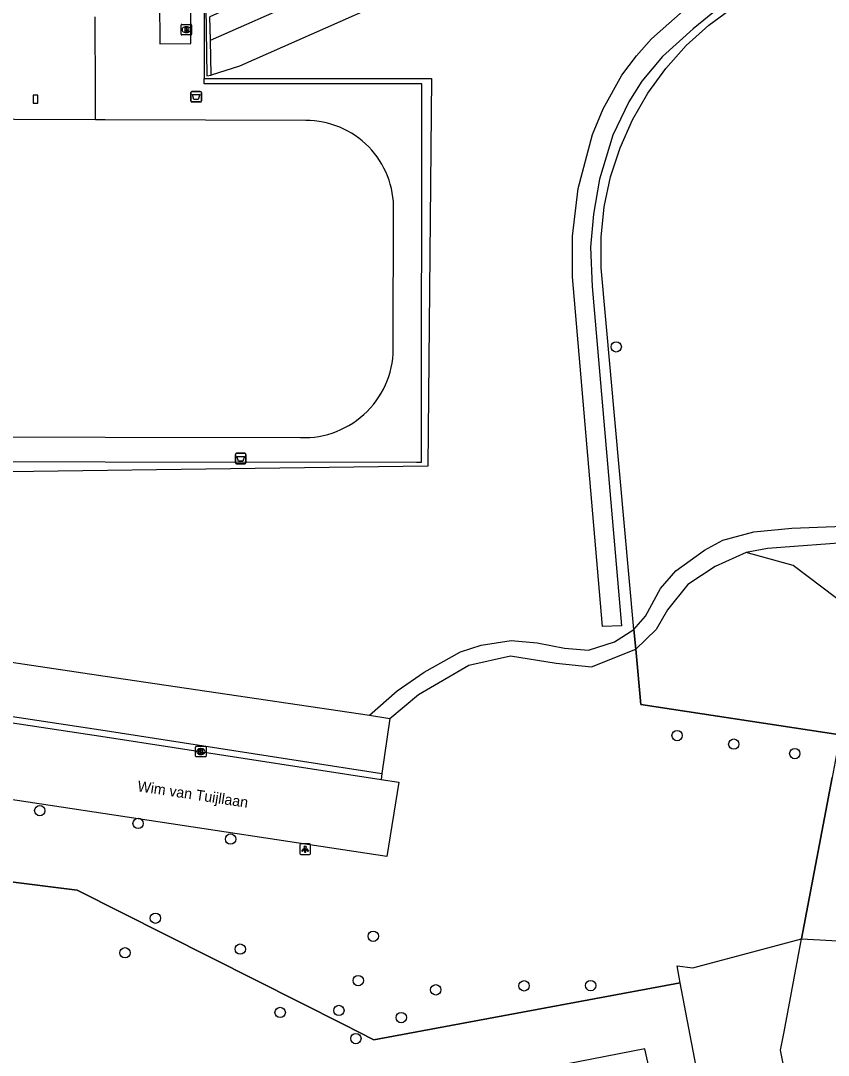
# Model space of a CAD drawing. Extents: x 160203 to 161526, y 379529 to 381797.
# Drawn here: x 160992 to 161068.4, y 380497.8 to 380595.6 of the extents above; entities that cross this region are included whole.
import ezdxf

# ---------------------------------------------------------------- set-up
doc = ezdxf.new("R2010")
doc.units = 0
for name, color, linetype in [('IMGEO_Afvalbak', 7, 'Continuous'), ('IMGEO_Boom', 7, 'Continuous'), ('IMGEO_Brandkraan', 7, 'Continuous'), ('IMGEO_Groenvoorziening', 7, 'Continuous'), ('IMGEO_Haag', 7, 'Continuous'), ('IMGEO_Hek', 7, 'Continuous'), ('IMGEO_Kademuur', 7, 'Continuous'), ('IMGEO_Kolk', 7, 'Continuous'), ('IMGEO_Lichtpunt', 7, 'Continuous'), ('IMGEO_Loofbos', 7, 'Continuous'), ('IMGEO_Open_loods', 7, 'Continuous'), ('IMGEO_Openbare_ruimte_label', 7, 'Continuous'), ('IMGEO_Parkeervlak_gesloten', 7, 'Continuous'), ('IMGEO_Rijbaan_lokaal_open', 7, 'Continuous'), ('IMGEO_Voetpad_gesloten', 7, 'Continuous'), ('IMGEO_Voetpad_halfverhard', 7, 'Continuous'), ('IMGEO_Voetpad_open', 7, 'Continuous'), ('IMGEO_Waterloop', 7, 'Continuous')]:
    doc.layers.add(name, color=color, linetype=linetype)

msp = doc.modelspace()

# ---------------------------------------------------------------- linework, layer by layer
at = {"layer": 'IMGEO_Afvalbak'}
for p, q in [((161008.103, 380588.053), (161008.103, 380588.853)), ((161008.103, 380588.853), (161008.103, 380588.053)), ((161008.203, 380588.953), (161008.993, 380588.953)), ((161008.993, 380588.953), (161008.203, 380588.953)), ((161009.093, 380588.853), (161009.093, 380588.053)), ((161009.093, 380588.053), (161009.093, 380588.853)), ((161008.993, 380587.953), (161008.203, 380587.953)), ((161008.203, 380587.953), (161008.993, 380587.953)), ((161012.315, 380553.824), (161012.315, 380554.624)), ((161012.315, 380554.624), (161012.315, 380553.824)), ((161012.415, 380554.724), (161013.205, 380554.724)), ((161013.205, 380554.724), (161012.415, 380554.724)), ((161013.305, 380554.624), (161013.305, 380553.824)), ((161013.305, 380553.824), (161013.305, 380554.624)), ((161013.205, 380553.724), (161012.415, 380553.724)), ((161012.415, 380553.724), (161013.205, 380553.724))]:
    msp.add_line(p, q, dxfattribs=at)
for points in [[(161008.246, 380588.667), (161008.95, 380588.667), (161008.801, 380588.197), (161008.395, 380588.197), (161008.246, 380588.667)], [(161012.458, 380554.438), (161013.162, 380554.438), (161013.013, 380553.968), (161012.607, 380553.968), (161012.458, 380554.438)]]:
    msp.add_lwpolyline(points, dxfattribs=at)
for centre, start, end in [((161008.203, 380588.853), 90, 180), ((161008.203, 380588.853), 90, 180), ((161008.993, 380588.853), 0, 90), ((161008.993, 380588.853), 360, 90), ((161008.203, 380588.053), 180, 270), ((161008.203, 380588.053), 180, 270), ((161008.993, 380588.053), 270, 0), ((161008.993, 380588.053), 270, 0), ((161012.415, 380554.624), 90, 180), ((161012.415, 380554.624), 90, 180), ((161013.205, 380554.624), 0, 90), ((161013.205, 380554.624), 360, 90), ((161012.415, 380553.824), 180, 270), ((161012.415, 380553.824), 180, 270), ((161013.205, 380553.824), 270, 0), ((161013.205, 380553.824), 270, 0)]:
    msp.add_arc(centre, 0.1, start, end, dxfattribs=at)
at = {"layer": 'IMGEO_Boom'}
for centre in [(161048.317, 380564.79), (161054.082, 380528.026), (161059.436, 380527.217), (161065.208, 380526.318), (160993.815, 380520.926), (161003.116, 380519.722), (161011.856, 380518.24), (161004.748, 380510.754), (161025.347, 380509.044), (161012.772, 380507.832), (161001.873, 380507.483), (161023.931, 380504.855), (161031.256, 380503.98), (161039.606, 380504.358), (161045.905, 380504.38), (161016.545, 380501.838), (161022.094, 380502.027), (161027.997, 380501.351), (161023.704, 380499.364)]:
    msp.add_circle(centre, 0.489, dxfattribs=at)
at = {"layer": 'IMGEO_Brandkraan'}
for p, q in [((161007.244, 380595.292), (161008.096, 380595.292)), ((161007.169, 380594.366), (161007.169, 380595.218)), ((161008.096, 380594.292), (161007.244, 380594.292)), ((161007.68, 380594.512), (161007.655, 380594.512)), ((161007.657, 380595.072), (161007.682, 380595.072)), ((161008.17, 380595.218), (161008.17, 380594.366))]:
    msp.add_line(p, q, dxfattribs=at)
for points in [[(161007.244, 380595.292), (161008.096, 380595.292)], [(161007.169, 380594.366), (161007.169, 380595.218)], [(161008.096, 380594.292), (161007.244, 380594.292)], [(161007.517, 380594.992), (161007.517, 380594.592), (161007.73, 380594.592)], [(161007.748, 380594.992), (161007.517, 380594.992)], [(161007.696, 380594.911), (161007.642, 380594.911), (161007.642, 380594.835)], [(161007.642, 380594.835), (161007.695, 380594.835)], [(161007.704, 380594.759), (161007.642, 380594.759), (161007.642, 380594.678)], [(161007.642, 380594.678), (161007.704, 380594.678)], [(161008.17, 380595.218), (161008.17, 380594.366)]]:
    msp.add_lwpolyline(points, dxfattribs=at)
for centre, radius, start, end in [((161007.246, 380595.216), 0.0765, 91.55205, 178.44795), ((161007.246, 380595.216), 0.0765, 91.55205, 178.44795), ((161008.094, 380595.216), 0.0765, 1.55205, 88.44795), ((161008.094, 380595.216), 0.0765, 1.55205, 88.44795), ((161007.246, 380594.368), 0.0765, 181.55205, 268.44795), ((161007.246, 380594.368), 0.0765, 181.55205, 268.44795), ((161007.697, 380594.873), 0.0379, 267.82845, 90.93552), ((161007.705, 380594.718), 0.0404, 269.87594, 90.50774), ((161007.736, 380594.843), 0.251, 268.66757, 293.53466), ((161007.752, 380594.847), 0.145, 59.4692, 91.53667), ((161007.777, 380594.894), 0.0922, 285.51372, 58.15012), ((161007.782, 380594.702), 0.105, 301.31148, 78.98903), ((161008.094, 380594.368), 0.0765, 271.55205, 358.44795), ((161008.094, 380594.368), 0.0765, 271.55205, 358.44795)]:
    msp.add_arc(centre, radius, start, end, dxfattribs=at)
for centre, major_axis, ratio, start_param, end_param in [((161007.656, 380594.792), (-0.387, 0.002), 0.722429, 4.712389, 7.853982), ((161007.681, 380594.792), (-0.39, 0.002), 0.717154, 1.570796, 4.712389)]:
    msp.add_ellipse(centre, major_axis=major_axis, ratio=ratio, start_param=start_param, end_param=end_param, dxfattribs=at)
at = {"layer": 'IMGEO_Groenvoorziening'}
msp.add_lwpolyline([(161092.862, 380626.998), (161089.63, 380625.323), (161075.362, 380619.305), (161056.631, 380610.785), (161012.701, 380591.353), (161010.016, 380590.501)], dxfattribs=at)
at = {"layer": 'IMGEO_Haag'}
msp.add_lwpolyline([(161009.355, 380590.18), (161030.84, 380590.175), (161030.513, 380553.498), (160974.535, 380552.751)], dxfattribs=at)
at = {"layer": 'IMGEO_Hek'}
for points in [[(161050.001, 380538.062), (161046.892, 380572.26), (161046.889, 380575.157), (161047.188, 380578.039), (161047.787, 380580.874), (161048.679, 380583.631), (161049.855, 380586.279), (161051.3, 380588.79), (161053.001, 380591.136), (161054.937, 380593.292), (161057.088, 380595.233), (161059.43, 380596.939), (161061.937, 380598.391), (161063.565, 380599.157), (161071.462, 380603.433), (161098.612, 380617.08)], [(161050.169, 380536.216), (161050.001, 380538.062)], [(161069.501, 380528.085), (161050.647, 380530.954), (161050.169, 380536.216)], [(161065.849, 380508.788), (161068.738, 380524.054)], [(160997.348, 380513.4), (160969.211, 380516.95)], [(161054.376, 380504.632), (161025.407, 380499.252), (161022.555, 380500.69), (160997.348, 380513.4)], [(161071.584, 380459.183), (161063.859, 380498.271), (161064.187, 380500), (161065.849, 380508.788)], [(161054.068, 380506.244), (161055.556, 380506.056)], [(161066.608, 380440.645), (161054.376, 380504.632), (161054.068, 380506.244)]]:
    msp.add_lwpolyline(points, dxfattribs=at)
at = {"layer": 'IMGEO_Kademuur'}
for points in [[(161009.826, 380599.136), (161009.487, 380599.094), (161009.596, 380590.439), (161010.016, 380590.501)], [(161009.943, 380593.804), (161009.895, 380595.997)], [(161010.016, 380590.501), (161009.943, 380593.804)]]:
    msp.add_lwpolyline(points, dxfattribs=at)
at = {"layer": 'IMGEO_Kolk'}
for p, q in [((161008.538, 380526.092), (161008.538, 380526.944)), ((161008.613, 380527.018), (161009.465, 380527.018)), ((161009.026, 380526.798), (161009.051, 380526.798)), ((161009.539, 380526.944), (161009.539, 380526.092)), ((161009.465, 380526.018), (161008.613, 380526.018)), ((161009.049, 380526.238), (161009.024, 380526.238))]:
    msp.add_line(p, q, dxfattribs=at)
for points in [[(161008.538, 380526.092), (161008.538, 380526.944)], [(161008.613, 380527.018), (161009.465, 380527.018)], [(161009.539, 380526.944), (161009.539, 380526.092)], [(161009.465, 380526.018), (161008.613, 380526.018)], [(161008.859, 380526.718), (161008.982, 380526.718), (161008.982, 380526.567), (161009.112, 380526.718), (161009.276, 380526.718), (161009.13, 380526.567), (161009.283, 380526.318), (161009.131, 380526.318), (161009.046, 380526.482), (161008.982, 380526.415), (161008.982, 380526.318), (161008.859, 380526.318), (161008.859, 380526.718)]]:
    msp.add_lwpolyline(points, dxfattribs=at)
for centre, start, end in [((161008.615, 380526.942), 91.55205, 178.44795), ((161008.615, 380526.942), 91.55205, 178.44795), ((161009.463, 380526.942), 1.55205, 88.44795), ((161009.463, 380526.942), 1.55205, 88.44795), ((161008.615, 380526.094), 181.55205, 268.44795), ((161008.615, 380526.094), 181.55205, 268.44795), ((161009.463, 380526.094), 271.55205, 358.44795), ((161009.463, 380526.094), 271.55205, 358.44795)]:
    msp.add_arc(centre, 0.0765, start, end, dxfattribs=at)
for centre, major_axis, ratio, start_param, end_param in [((161009.025, 380526.518), (-0.387, 0.002), 0.722429, 4.712389, 7.853982), ((161009.05, 380526.518), (-0.39, 0.002), 0.717154, 1.570796, 4.712389)]:
    msp.add_ellipse(centre, major_axis=major_axis, ratio=ratio, start_param=start_param, end_param=end_param, dxfattribs=at)
at = {"layer": 'IMGEO_Lichtpunt'}
for p, q in [((161018.413, 380517.688), (161018.413, 380516.881)), ((161018.413, 380517.688), (161018.413, 380516.881)), ((161019.315, 380517.783), (161018.507, 380517.783)), ((161019.315, 380517.783), (161018.507, 380517.783)), ((161019.409, 380516.881), (161019.409, 380517.688)), ((161019.409, 380516.881), (161019.409, 380517.688)), ((161018.507, 380516.787), (161019.315, 380516.787)), ((161018.507, 380516.787), (161019.315, 380516.787))]:
    msp.add_line(p, q, dxfattribs=at)
for points in [[(161018.787, 380517.352), (161018.826, 380517.324), (161018.638, 380517.062), (161018.6, 380517.089), (161018.787, 380517.352)], [(161018.889, 380517.304), (161018.936, 380517.304), (161018.936, 380516.982), (161018.889, 380516.982), (161018.889, 380517.304)], [(161018.999, 380517.324), (161019.037, 380517.351), (161019.224, 380517.089), (161019.185, 380517.061), (161018.999, 380517.324)]]:
    msp.add_lwpolyline(points, dxfattribs=at)
msp.add_circle((161018.912, 380517.486), 0.0994, dxfattribs=at)
for centre, start, end in [((161018.507, 380517.688), 90, 180), ((161018.507, 380517.688), 90, 180), ((161019.315, 380517.688), 0, 90), ((161019.315, 380517.688), 0, 90), ((161018.507, 380516.881), 180, 270), ((161018.507, 380516.881), 180, 270), ((161019.315, 380516.881), 270, 0), ((161019.315, 380516.881), 270, 360)]:
    msp.add_arc(centre, 0.0946, start, end, dxfattribs=at)
at = {"layer": 'IMGEO_Loofbos'}
for points in [[(161151.663, 380559.856), (161149.809, 380560.422), (161148.111, 380560.705), (161147.184, 380560.783), (161139.902, 380564.161), (161132.57, 380561.521), (161125.881, 380556.731), (161120.038, 380549.051), (161118.235, 380546.156), (161117.164, 380542.115), (161112.955, 380538.902), (161107.161, 380533.448), (161103.947, 380533.448), (161095.669, 380533.448), (161090.58, 380531.058), (161087.61, 380529.159), (161083.373, 380529.159), (161074.252, 380530.662), (161072.904, 380535.976), (161070.469, 380540.017), (161065.065, 380544.108), (161060.622, 380545.329)], [(161050.169, 380536.216), (161050.647, 380530.954), (161069.501, 380528.085), (161068.738, 380524.054), (161065.849, 380508.788)], [(160969.211, 380516.95), (160997.348, 380513.4), (161022.555, 380500.69), (161025.407, 380499.252), (161054.376, 380504.632)], [(161054.376, 380504.632), (161054.068, 380506.244), (161055.556, 380506.056), (161065.849, 380508.788)], [(161071.584, 380459.183), (161063.859, 380498.271), (161064.187, 380500), (161065.849, 380508.788)], [(161065.849, 380508.788), (161095.124, 380507.205), (161101.207, 380496.804), (161106.581, 380489.158), (161112.821, 380486.036), (161120.126, 380484.817), (161135.383, 380484.055)], [(161066.608, 380440.645), (161054.376, 380504.632)]]:
    msp.add_lwpolyline(points, dxfattribs=at)
at = {"layer": 'IMGEO_Open_loods'}
for points in [[(160993.64, 380588.613), (160993.205, 380588.614), (160993.203, 380587.836), (160993.638, 380587.835), (160993.64, 380588.613)], [(160999.085, 380586.28), (160976.111, 380586.373)], [(161018.973, 380586.199), (161000, 380586.276), (160999.085, 380586.28)], [(161027.237, 380565.008), (161027.267, 380577.721)], [(160975.708, 380556.3), (161000, 380556.251), (161018.465, 380556.213)]]:
    msp.add_lwpolyline(points, dxfattribs=at)
for centre, radius, start, end in [((161019.012, 380577.941), 8.258, 358.47159, 90.27132), ((161018.785, 380564.666), 8.459, 267.8303, 2.31973)]:
    msp.add_arc(centre, radius, start, end, dxfattribs=at)
at = {"layer": 'IMGEO_Parkeervlak_gesloten'}
for points in [[(160940.686, 380542.511), (161000, 380533.651), (161024.98, 380529.951)], [(161026.899, 380529.633), (161026.173, 380524.441)]]:
    msp.add_lwpolyline(points, dxfattribs=at)
at = {"layer": 'IMGEO_Rijbaan_lokaal_open'}
for points in [[(160828.18, 380554.482), (161000, 380528.513), (161026.173, 380524.441)], [(160828.089, 380553.895), (161000, 380527.913), (161026.094, 380523.879)], [(161026.094, 380523.879), (161027.779, 380523.619), (161026.638, 380516.587), (161000, 380520.618), (160970.441, 380525.091)], [(161026.173, 380524.441), (161026.094, 380523.879)]]:
    msp.add_lwpolyline(points, dxfattribs=at)
at = {"layer": 'IMGEO_Voetpad_gesloten'}
for points in [[(161009.357, 380600.463), (161009.355, 380590.18)], [(161005.154, 380593.467), (161008.113, 380593.501), (161008.084, 380597.558), (161005.145, 380597.544), (161005.154, 380593.467)], [(160999.085, 380586.28), (160999.079, 380588.766), (160999.062, 380595.993)], [(160974.556, 380553.755), (160974.56, 380553.97), (161000, 380553.934), (161029.421, 380553.892), (161029.796, 380553.891), (161029.912, 380553.891), (161029.94, 380589.66), (161029.824, 380589.66), (161009.355, 380589.664), (161009.355, 380590.18)]]:
    msp.add_lwpolyline(points, dxfattribs=at)
at = {"layer": 'IMGEO_Voetpad_halfverhard'}
for points in [[(161050.001, 380538.062), (161051.094, 380539.336), (161052.513, 380541.948), (161053.96, 380543.623), (161056.657, 380545.553), (161058.406, 380546.515), (161061.337, 380547.31), (161064.913, 380547.658), (161084.433, 380548.403), (161088.698, 380549.105), (161093.665, 380550.794), (161098.483, 380554.073), (161102.357, 380558.942), (161107.473, 380566.345), (161110.734, 380572.672), (161111.727, 380576.995), (161111.131, 380581.218), (161109.293, 380585.292), (161106.766, 380588.683), (161105.276, 380592.061), (161103.29, 380598.42), (161101.432, 380606.57), (161099.65, 380615.748), (161099.2, 380619.612)], [(161110.282, 380585.876), (161112.352, 380581.457), (161112.97, 380577.598), (161113.018, 380576.024), (161112.402, 380573.38), (161111.393, 380570.821), (161109.577, 380567.219), (161107.537, 380564.015), (161101.439, 380555.158), (161099.317, 380552.929), (161097.131, 380551.169), (161094.519, 380549.535), (161089.296, 380547.686), (161085.683, 380546.999), (161081.758, 380546.74), (161071.041, 380546.351), (161062.633, 380545.737), (161060.622, 380545.329)], [(161060.622, 380545.329), (161057.681, 380544.023), (161055.102, 380542.32), (161053.166, 380539.932), (161052.087, 380538.058), (161050.169, 380536.216)], [(161024.98, 380529.951), (161027.619, 380532.25), (161030.174, 380534.01), (161033.608, 380535.941), (161035.538, 380536.566), (161038.376, 380537.02), (161040.831, 380536.814), (161043.442, 380536.303), (161045.685, 380536.12), (161048.145, 380536.889), (161050.001, 380538.062)], [(161050.001, 380538.062), (161050.169, 380536.216)], [(161026.899, 380529.633), (161029.618, 380531.911), (161034.399, 380534.694), (161038.31, 380535.563), (161042.657, 380534.867), (161045.973, 380534.533), (161050.169, 380536.216)], [(161024.98, 380529.951), (161026.899, 380529.633)]]:
    msp.add_lwpolyline(points, dxfattribs=at)
at = {"layer": 'IMGEO_Voetpad_open'}
msp.add_lwpolyline([(161066.608, 380440.645), (161066.33, 380440.623), (161063.889, 380442.387), (161063.307, 380444.833), (161051.214, 380497.538), (161051.027, 380498.401), (160975.678, 380483.713)], dxfattribs=at)
at = {"layer": 'IMGEO_Waterloop'}
for points in [[(161009.943, 380593.804), (161062.339, 380616.92), (161090.054, 380628.954), (161091.21, 380629.729), (161091.337, 380630.37), (161091.256, 380630.519), (161091.915, 380630.792), (161091.4, 380631.789), (161090.762, 380631.536), (161090.661, 380631.756), (161089.88, 380631.882), (161065.601, 380621.17), (161009.895, 380595.997)], [(161050.23, 380592.304), (161051.665, 380593.915), (161055.472, 380597.303), (161062.72, 380602.112), (161066.147, 380604.104), (161097.422, 380620.092)], [(161098.311, 380617.986), (161065.436, 380601.414), (161060.994, 380598.8), (161057.973, 380596.783), (161055.612, 380594.88), (161052.693, 380592.253), (161050.738, 380589.918), (161049.507, 380587.964), (161048.009, 380584.83), (161046.752, 380580.656), (161046.181, 380577.357), (161045.902, 380574.21), (161046.054, 380570.492), (161048.834, 380538.421), (161047.032, 380538.335), (161044.176, 380571.431), (161044.201, 380575.25), (161044.734, 380579.78), (161046.08, 380584.894), (161047.095, 380587.292), (161048.859, 380590.477), (161050.23, 380592.304)]]:
    msp.add_lwpolyline(points, dxfattribs=at)

# ---------------------------------------------------------------- texts
at = {"layer": 'IMGEO_Openbare_ruimte_label'}
msp.add_text('Wim van Tuijllaan', height=1, rotation=351.37577, dxfattribs=at).set_placement((161003.002, 380522.776))

doc.saveas('drawing.dxf')
